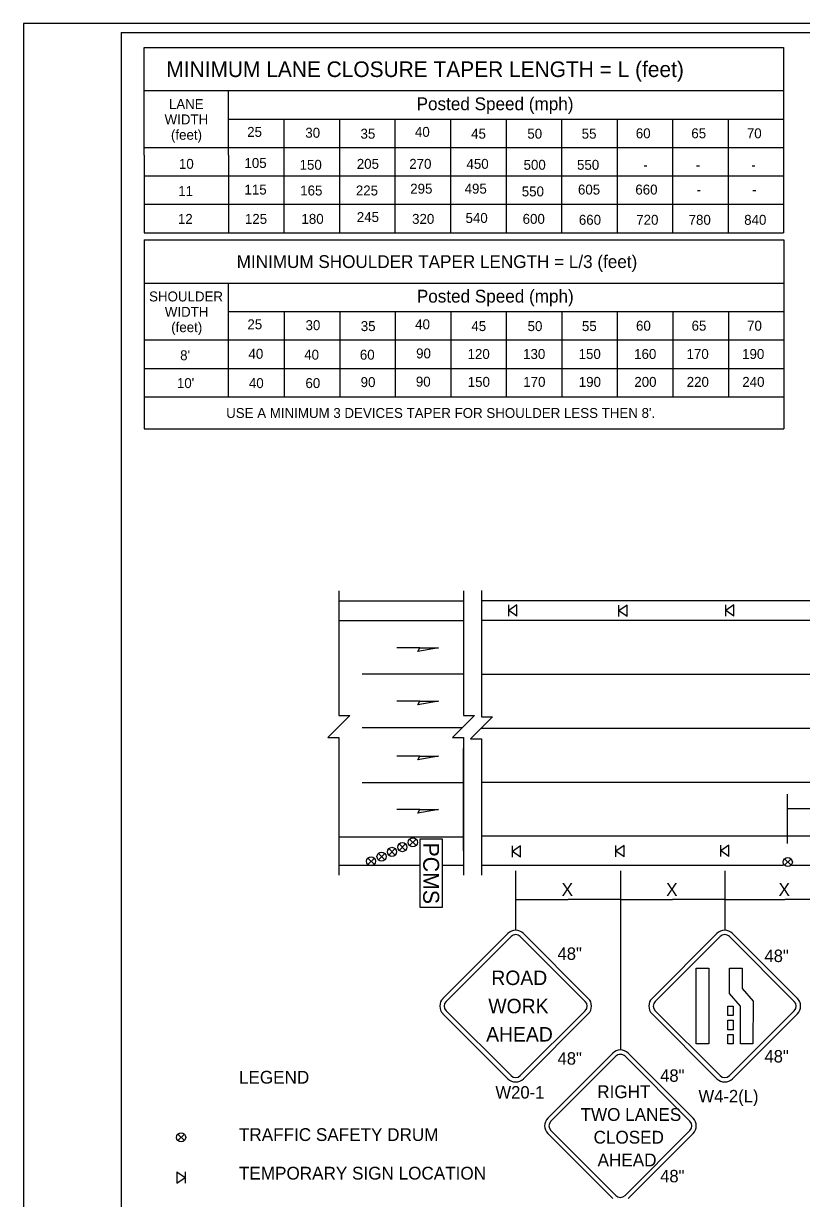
# Model space of a CAD drawing. Extents: x 99988 to 100172, y 99995 to 100047.
# Drawn here: x 99999.31 to 100004.79, y 100002.17 to 100010.44 of the extents above; entities that cross this region are included whole.
import ezdxf

# ---------------------------------------------------------------- set-up
doc = ezdxf.new("R2010")
doc.units = 0
for name, color, linetype in [('Default', 7, 'Continuous'), ('Level 15', 7, 'Continuous'), ('Level 20', 7, 'Continuous'), ('SH_DE_DetailBody1Text', 7, 'Continuous'), ('SH_DE_DetailHeading2Text', 7, 'Continuous'), ('SH_GI_PlotLimits', 7, 'Continuous'), ('SH_GI_SheetBorder', 7, 'Continuous'), ('SH_GI_TrafficMvmntArrowRt1Lane', 7, 'Continuous'), ('SH_TI_MinTaperLength25to35Note', 7, 'Continuous'), ('SH_TI_MinTaperLength25to70Note', 7, 'Continuous'), ('TR_SN_WarningSigns', 7, 'Continuous'), ('TR_WZ_PortableChangeMessageSign', 7, 'Continuous'), ('TR_WZ_WorkZoneDetails', 7, 'Continuous')]:
    doc.layers.add(name, color=color, linetype=linetype)

msp = doc.modelspace()

# ---------------------------------------------------------------- linework, layer by layer
at = {"layer": 'Default'}
for p, q in [((100002.7845, 100006.3463), (100002.7267, 100006.3061)), ((100002.7267, 100006.2659), (100002.7267, 100006.3463)), ((100002.7845, 100006.2659), (100002.7845, 100006.3463)), ((100003.5589, 100006.3444), (100003.5012, 100006.3041)), ((100003.5012, 100006.264), (100003.5012, 100006.3444)), ((100003.5589, 100006.264), (100003.5589, 100006.3444)), ((100004.3113, 100006.3463), (100004.2535, 100006.3061)), ((100004.2535, 100006.2659), (100004.2535, 100006.3463)), ((100004.3113, 100006.2659), (100004.3113, 100006.3463)), ((100002.7845, 100006.2659), (100002.7267, 100006.3061)), ((100003.5589, 100006.264), (100003.5012, 100006.3041)), ((100004.3113, 100006.2659), (100004.2535, 100006.3061)), ((100001.6952, 100005.8622), (100002.4121, 100005.8622)), ((100002.5342, 100005.8585), (100011.4419, 100005.8585)), ((100001.6952, 100005.4826), (100002.4024, 100005.4826)), ((100002.5316, 100005.4785), (100014.1914, 100005.4785)), ((100001.6952, 100005.0976), (100002.4092, 100005.0976)), ((100002.5342, 100005.0998), (100011.6853, 100005.0998)), ((100001.956, 100004.619), (100002.0013, 100004.6643)), ((100002.0013, 100004.619), (100001.956, 100004.6643)), ((100002.0294, 100004.6523), (100002.0747, 100004.6976)), ((100002.0747, 100004.6523), (100002.0294, 100004.6976)), ((100004.2763, 100004.6556), (100004.2186, 100004.6153)), ((100004.2186, 100004.5751), (100004.2186, 100004.6556)), ((100004.2763, 100004.5751), (100004.2763, 100004.6556)), ((100001.8092, 100004.5525), (100001.8545, 100004.5978)), ((100001.8545, 100004.5525), (100001.8092, 100004.5978)), ((100001.8826, 100004.5858), (100001.9279, 100004.631)), ((100001.9279, 100004.5858), (100001.8826, 100004.631)), ((100002.81, 100004.6508), (100002.7523, 100004.6105)), ((100002.7523, 100004.5703), (100002.7523, 100004.6508)), ((100002.81, 100004.5703), (100002.7523, 100004.6105)), ((100002.81, 100004.5703), (100002.81, 100004.6508)), ((100003.5389, 100004.6543), (100003.4812, 100004.614)), ((100003.4812, 100004.5739), (100003.4812, 100004.6543)), ((100003.5389, 100004.5739), (100003.4812, 100004.614)), ((100003.5389, 100004.5739), (100003.5389, 100004.6543)), ((100004.2763, 100004.5751), (100004.2186, 100004.6153)), ((100001.7358, 100004.5192), (100001.7811, 100004.5645)), ((100001.7811, 100004.5192), (100001.7358, 100004.5645)), ((100004.7129, 100004.5589), (100004.6677, 100004.5137)), ((100004.6677, 100004.5589), (100004.7129, 100004.5137)), ((100000.4442, 100002.5769), (100000.3989, 100002.6222)), ((100000.4442, 100002.6222), (100000.3989, 100002.5769)), ((100000.3916, 100002.3575), (100000.4494, 100002.3174)), ((100000.3916, 100002.3575), (100000.3916, 100002.2771)), ((100000.4494, 100002.3575), (100000.4494, 100002.2771)), ((100000.3916, 100002.2771), (100000.4494, 100002.3174))]:
    msp.add_line(p, q, dxfattribs=at)
for centre in [(100001.9786, 100004.6417), (100002.052, 100004.6749), (100001.7584, 100004.5419), (100001.8318, 100004.5751), (100001.9052, 100004.6084), (100004.6903, 100004.5363), (100000.4216, 100002.5995)]:
    msp.add_circle(centre, 0.032, dxfattribs=at)
at = {"layer": 'Level 15'}
for p, q in [((100004.6854, 100004.9138), (100004.8899, 100004.9138)), ((100002.7755, 100004.2732), (100003.144, 100004.2732)), ((100003.5125, 100004.2732), (100003.144, 100004.2732)), ((100003.5125, 100004.2732), (100003.8795, 100004.2732)), ((100004.2465, 100004.2732), (100003.8795, 100004.2732)), ((100004.2465, 100004.2732), (100004.6704, 100004.2732)), ((100005.0944, 100004.2732), (100004.6704, 100004.2732))]:
    msp.add_line(p, q, dxfattribs=at)
at = {"layer": 'SH_GI_PlotLimits'}
msp.add_lwpolyline([(99999.3125, 99999.9375), (100015.8125, 99999.9375), (100015.8125, 100010.4375), (99999.3125, 100010.4375)], close=True, dxfattribs=at)
at = {"layer": 'SH_GI_SheetBorder'}
for q in [(100000, 100000), (100015.75, 100010.375)]:
    msp.add_line((100000, 100010.375), q, dxfattribs=at)
at = {"layer": 'SH_GI_TrafficMvmntArrowRt1Lane'}
for p, q in [((100002.1012, 100006.0451), (100001.9404, 100006.0451)), ((100002.1012, 100005.6684), (100001.9404, 100005.6684)), ((100002.1012, 100005.2821), (100001.9404, 100005.2821)), ((100002.1012, 100004.9072), (100001.9404, 100004.9072))]:
    msp.add_line(p, q, dxfattribs=at)
for points in [[(100002.2322, 100006.0451), (100002.0863, 100006.0194), (100002.1012, 100006.0451)], [(100002.2322, 100005.6684), (100002.0863, 100005.6427), (100002.1012, 100005.6684)], [(100002.2322, 100005.2821), (100002.0863, 100005.2563), (100002.1012, 100005.2821)], [(100002.2322, 100004.9072), (100002.0863, 100004.8815), (100002.1012, 100004.9072)]]:
    msp.add_lwpolyline(points, close=True, dxfattribs=at)
at = {"layer": 'SH_TI_MinTaperLength25to35Note'}
for p, q in [((100000.1627, 100008.9145), (100004.6627, 100008.9145)), ((100000.1627, 100008.9145), (100000.1627, 100008.2042)), ((100004.6627, 100008.9145), (100004.6627, 100008.2042)), ((100000.1627, 100008.6113), (100004.6627, 100008.6113)), ((100000.7559, 100008.2042), (100000.7559, 100008.6113)), ((100000.7559, 100008.4113), (100004.6627, 100008.4113)), ((100001.1465, 100008.4113), (100001.1465, 100008.2042)), ((100001.5372, 100008.4113), (100001.5372, 100008.2042)), ((100001.9279, 100008.4113), (100001.9279, 100008.2042)), ((100002.3186, 100008.4113), (100002.3186, 100008.2042)), ((100002.7093, 100008.4113), (100002.7093, 100008.2042)), ((100003.1, 100008.4113), (100003.1, 100008.2042)), ((100003.4907, 100008.4113), (100003.4907, 100008.2042)), ((100003.8813, 100008.4113), (100003.8813, 100008.2042)), ((100004.2719, 100008.4113), (100004.2719, 100008.2042)), ((100000.1627, 100008.2113), (100004.6627, 100008.2113)), ((100000.1627, 100008.2042), (100000.1627, 100007.5845)), ((100000.7559, 100007.8096), (100000.7559, 100008.2042)), ((100001.1465, 100008.2042), (100001.1465, 100007.8096)), ((100001.5372, 100008.2042), (100001.5372, 100007.8096)), ((100001.9279, 100008.2042), (100001.9279, 100007.8096)), ((100002.3186, 100008.2042), (100002.3186, 100007.8096)), ((100002.7093, 100008.2042), (100002.7093, 100007.8096)), ((100003.1, 100008.2042), (100003.1, 100007.8096)), ((100003.4907, 100008.2042), (100003.4907, 100007.8096)), ((100003.8813, 100008.2042), (100003.8813, 100007.8096)), ((100004.2719, 100008.2042), (100004.2719, 100007.8096)), ((100004.6627, 100008.2042), (100004.6627, 100007.5845)), ((100000.1627, 100008.0096), (100004.6627, 100008.0096)), ((100000.1627, 100007.8096), (100004.6627, 100007.8096)), ((100000.1627, 100007.5845), (100004.6627, 100007.5845))]:
    msp.add_line(p, q, dxfattribs=at)
at = {"layer": 'SH_TI_MinTaperLength25to70Note'}
for p, q in [((100000.1611, 100010.2684), (100004.6611, 100010.2684)), ((100000.1611, 100009.5102), (100000.1611, 100010.2684)), ((100004.6611, 100010.2684), (100004.6611, 100008.9652)), ((100000.1611, 100009.9652), (100004.6611, 100009.9652)), ((100000.7542, 100009.5102), (100000.7542, 100009.9652)), ((100000.7542, 100009.7652), (100004.6611, 100009.7652)), ((100001.1449, 100009.7652), (100001.1449, 100008.9652)), ((100001.5356, 100009.7652), (100001.5356, 100008.9652)), ((100001.9263, 100009.7652), (100001.9263, 100008.9652)), ((100002.3169, 100009.7652), (100002.3169, 100008.9652)), ((100002.7076, 100009.7652), (100002.7076, 100008.9652)), ((100003.0983, 100009.7652), (100003.0983, 100008.9652)), ((100003.489, 100009.7652), (100003.489, 100008.9652)), ((100003.8796, 100009.7652), (100003.8796, 100008.9652)), ((100004.2703, 100009.7652), (100004.2703, 100008.9652)), ((100000.1611, 100009.5652), (100004.6611, 100009.5652)), ((100000.1611, 100009.5102), (100000.1611, 100008.9652)), ((100000.7542, 100009.5102), (100000.7542, 100008.9652)), ((100000.1611, 100009.3652), (100004.6611, 100009.3652)), ((100000.1611, 100009.1652), (100004.6611, 100009.1652)), ((100000.1611, 100008.9652), (100004.6611, 100008.9652))]:
    msp.add_line(p, q, dxfattribs=at)
at = {"layer": 'TR_SN_WarningSigns'}
for p, q in [((100002.2642, 100003.5777), (100002.7212, 100004.0346)), ((100002.286, 100003.556), (100002.7429, 100004.0129)), ((100002.8082, 100004.0129), (100003.2651, 100003.5559)), ((100002.8299, 100004.0346), (100003.2868, 100003.5777)), ((100003.7351, 100003.5777), (100004.1921, 100004.0346)), ((100003.7569, 100003.556), (100004.2138, 100004.0129)), ((100004.2791, 100004.0129), (100004.736, 100003.556)), ((100004.3009, 100004.0346), (100004.7577, 100003.5777)), ((100002.7211, 100003.012), (100002.2642, 100003.4689)), ((100002.7429, 100003.0338), (100002.286, 100003.4907)), ((100003.2651, 100003.4907), (100002.8082, 100003.0338)), ((100003.2868, 100003.4689), (100002.8299, 100003.012)), ((100004.1921, 100003.0121), (100003.7351, 100003.4689)), ((100004.2138, 100003.0338), (100003.7569, 100003.4907)), ((100004.736, 100003.4907), (100004.2791, 100003.0338)), ((100004.7577, 100003.4689), (100004.3009, 100003.0121)), ((100003.0011, 100002.7348), (100003.4581, 100003.1917)), ((100003.0229, 100002.7131), (100003.4798, 100003.17)), ((100003.5451, 100003.17), (100004.002, 100002.7131)), ((100003.5668, 100003.1917), (100004.0237, 100002.7348)), ((100003.4581, 100002.1692), (100003.0011, 100002.626)), ((100003.4798, 100002.1909), (100003.0229, 100002.6478)), ((100004.002, 100002.6478), (100003.5451, 100002.1909)), ((100004.0237, 100002.626), (100003.5668, 100002.1692))]:
    msp.add_line(p, q, dxfattribs=at)
for points in [[(100004.135, 100003.2567), (100004.0454, 100003.2567), (100004.0454, 100003.79), (100004.135, 100003.79)], [(100004.3696, 100003.79), (100004.3696, 100003.6462), (100004.4475, 100003.557), (100004.4436, 100003.2567), (100004.3579, 100003.2567), (100004.3579, 100003.5234), (100004.2801, 100003.6126), (100004.2801, 100003.79)], [(100004.3068, 100003.4567), (100004.2673, 100003.4567), (100004.2673, 100003.5233), (100004.3068, 100003.5233)], [(100004.3068, 100003.3567), (100004.2673, 100003.3567), (100004.2673, 100003.4233), (100004.3068, 100003.4233)], [(100004.3068, 100003.2567), (100004.2673, 100003.2567), (100004.2673, 100003.3233), (100004.3068, 100003.3233)]]:
    msp.add_lwpolyline(points, close=True, dxfattribs=at)
for centre, radius, start, end in [((100002.7755, 100003.9802), 0.0769, 44.99627, 134.99965), ((100002.7755, 100003.9802), 0.0462, 44.99627, 134.99965), ((100004.2465, 100003.9802), 0.0769, 44.99627, 134.99965), ((100004.2465, 100003.9802), 0.0462, 44.99627, 134.99965), ((100002.3186, 100003.5233), 0.0769, 134.99657, 224.99357), ((100002.3186, 100003.5233), 0.0462, 134.99657, 224.99357), ((100003.2324, 100003.5233), 0.0462, 314.99936, 44.99485), ((100003.2324, 100003.5233), 0.0769, 314.99936, 44.99485), ((100003.7896, 100003.5233), 0.0769, 134.99657, 224.99357), ((100003.7896, 100003.5233), 0.0462, 134.99657, 224.99357), ((100004.7034, 100003.5233), 0.0462, 314.99936, 44.99485), ((100004.7034, 100003.5233), 0.0769, 314.99936, 44.99485), ((100003.5125, 100003.1373), 0.0769, 44.99627, 134.99965), ((100003.5125, 100003.1373), 0.0462, 44.99627, 134.99965), ((100002.7755, 100003.0664), 0.0769, 225, 314.99958), ((100002.7755, 100003.0664), 0.0462, 225, 314.99958), ((100004.2464, 100003.0664), 0.0769, 225, 314.99958), ((100004.2464, 100003.0664), 0.0462, 225, 314.99958), ((100003.0556, 100002.6804), 0.0769, 134.99657, 224.99357), ((100003.0556, 100002.6804), 0.0462, 134.99657, 224.99357), ((100003.9693, 100002.6804), 0.0462, 314.99936, 44.99485), ((100003.9693, 100002.6804), 0.0769, 314.99936, 44.99485), ((100003.5124, 100002.2235), 0.0462, 225, 314.99958)]:
    msp.add_arc(centre, radius, start, end, dxfattribs=at)
at = {"layer": 'TR_WZ_PortableChangeMessageSign'}
msp.add_lwpolyline([(100002.1008, 100004.6986), (100002.1008, 100004.2186), (100002.2608, 100004.2186), (100002.2608, 100004.6986)], close=True, dxfattribs=at)
at = {"layer": 'TR_WZ_WorkZoneDetails'}
for p, q in [((100001.5316, 100006.3745), (100002.4092, 100006.3745)), ((100002.5342, 100006.3767), (100014.2093, 100006.3767)), ((100001.5365, 100006.2357), (100002.4092, 100006.2357)), ((100002.5342, 100006.2379), (100009.125, 100006.2379)), ((100002.4092, 100004.615), (100002.4092, 100005.3363)), ((100004.6854, 100005.0138), (100004.6854, 100004.6683)), ((100001.5316, 100004.7142), (100002.4092, 100004.7142)), ((100002.5342, 100004.7201), (100005.0601, 100004.7201)), ((100001.5316, 100004.5142), (100002.0987, 100004.5142)), ((100002.2608, 100004.5142), (100002.4092, 100004.5142)), ((100002.5342, 100004.5142), (100004.658, 100004.5142)), ((100004.7166, 100004.5142), (100005.3535, 100004.5142)), ((100002.7755, 100004.4751), (100002.7755, 100004.0572)), ((100003.5125, 100004.4751), (100003.5125, 100003.2143)), ((100004.2465, 100004.4751), (100004.2465, 100004.0572))]:
    msp.add_line(p, q, dxfattribs=at)
for points in [[(100001.5316, 100006.4453), (100001.5316, 100005.5668), (100001.609, 100005.5668), (100001.4542, 100005.412), (100001.5316, 100005.412), (100001.5316, 100004.4434)], [(100002.4092, 100006.4453), (100002.4092, 100005.5668), (100002.4866, 100005.5668), (100002.3318, 100005.412), (100002.4092, 100005.412), (100002.4092, 100004.4434)], [(100002.5342, 100006.4475), (100002.5342, 100005.5586), (100002.6116, 100005.5586), (100002.4568, 100005.4037), (100002.5342, 100005.4037), (100002.5342, 100004.4434)]]:
    msp.add_lwpolyline(points, dxfattribs=at)

# ---------------------------------------------------------------- texts
at = {"layer": 'Level 20'}
for p in [(100003.0989, 100004.2982), (100003.8344, 100004.2982), (100004.6254, 100004.2982)]:
    msp.add_text('X', height=0.09, dxfattribs=at).set_placement(p)
at = {"layer": 'SH_DE_DetailBody1Text'}
for s, p in [('TRAFFIC SAFETY DRUM', (100000.8284, 100002.5738)), ('TEMPORARY SIGN LOCATION', (100000.8284, 100002.3023))]:
    msp.add_text(s, height=0.09, dxfattribs=at).set_placement(p)
at = {"layer": 'SH_DE_DetailHeading2Text'}
msp.add_text('LEGEND', height=0.09, dxfattribs=at).set_placement((100000.8284, 100002.9775))
at = {"layer": 'SH_TI_MinTaperLength25to35Note'}
for s, height, p in [('MINIMUM SHOULDER TAPER LENGTH = L/3 (feet)', 0.09, (100000.8125, 100008.7169)), ('SHOULDER', 0.07, (100000.1961, 100008.4817)), ('Posted Speed (mph)', 0.09, (100002.0802, 100008.4737)), ('WIDTH', 0.07, (100000.307, 100008.3736)), ('(feet)', 0.07, (100000.3518, 100008.2656)), ('25', 0.07, (100000.888, 100008.2858)), ('30', 0.07, (100001.2971, 100008.2796)), ('35', 0.07, (100001.6856, 100008.2731)), ('40', 0.07, (100002.0684, 100008.2858)), ('45', 0.07, (100002.4638, 100008.2731)), ('50', 0.07, (100002.8594, 100008.2731)), ('55', 0.07, (100003.2417, 100008.2731)), ('60', 0.07, (100003.6225, 100008.2758)), ('65', 0.07, (100004.0132, 100008.2758)), ('70', 0.07, (100004.4039, 100008.2758)), ("8'", 0.07, (100000.4148, 100008.0679)), ('40', 0.07, (100000.8955, 100008.0783)), ('40', 0.07, (100001.2877, 100008.0717)), ('60', 0.07, (100001.6792, 100008.0717)), ('90', 0.07, (100002.075, 100008.0809)), ('120', 0.07, (100002.4371, 100008.0769)), ('130', 0.07, (100002.8278, 100008.0769)), ('150', 0.07, (100003.2184, 100008.0769)), ('160', 0.07, (100003.6091, 100008.0769)), ('170', 0.07, (100003.9778, 100008.0769)), ('190', 0.07, (100004.3688, 100008.0769)), ("10'", 0.07, (100000.3919, 100007.8719)), ('40', 0.07, (100000.8984, 100007.8719)), ('60', 0.07, (100001.2964, 100007.8719)), ('90', 0.07, (100001.6847, 100007.879)), ('90', 0.07, (100002.0733, 100007.8822)), ('150', 0.07, (100002.4383, 100007.8805)), ('170', 0.07, (100002.8289, 100007.8805)), ('190', 0.07, (100003.2196, 100007.8805)), ('200', 0.07, (100003.6103, 100007.8805)), ('220', 0.07, (100003.979, 100007.8805)), ('240', 0.07, (100004.37, 100007.8805)), ("USE A MINIMUM 3 DEVICES TAPER FOR SHOULDER LESS THEN 8'.", 0.07, (100000.7386, 100007.6618))]:
    msp.add_text(s, height=height, dxfattribs=at).set_placement(p)
at = {"layer": 'SH_TI_MinTaperLength25to70Note'}
for s, height, p in [('MINIMUM LANE CLOSURE TAPER LENGTH = L (feet)', 0.11, (100000.3178, 100010.0608)), ('LANE', 0.07, (100000.3356, 100009.8356)), ('Posted Speed (mph)', 0.09, (100002.0785, 100009.8276)), ('WIDTH', 0.07, (100000.3053, 100009.7275)), ('25', 0.07, (100000.8863, 100009.6397)), ('30', 0.07, (100001.2954, 100009.6335)), ('40', 0.07, (100002.0668, 100009.6397)), ('60', 0.07, (100003.6209, 100009.6297)), ('65', 0.07, (100004.0116, 100009.6297)), ('70', 0.07, (100004.4022, 100009.6297)), ('(feet)', 0.07, (100000.3501, 100009.6195)), ('35', 0.07, (100001.6839, 100009.627)), ('45', 0.07, (100002.4622, 100009.627)), ('50', 0.07, (100002.8578, 100009.627)), ('55', 0.07, (100003.2401, 100009.627)), ('10', 0.07, (100000.4062, 100009.4147)), ('105', 0.07, (100000.8671, 100009.4209)), ('150', 0.07, (100001.2552, 100009.4081)), ('205', 0.07, (100001.6576, 100009.4147)), ('270', 0.07, (100002.0267, 100009.4147)), ('450', 0.07, (100002.4293, 100009.4147)), ('500', 0.07, (100002.8311, 100009.4081)), ('550', 0.07, (100003.2072, 100009.4081)), ('-', 0.07, (100003.6736, 100009.4081)), ('-', 0.07, (100004.0423, 100009.4081)), ('-', 0.07, (100004.4333, 100009.4081)), ('11', 0.07, (100000.4012, 100009.2235)), ('115', 0.07, (100000.8674, 100009.2339)), ('165', 0.07, (100001.2595, 100009.2274)), ('225', 0.07, (100001.6511, 100009.2274)), ('295', 0.07, (100002.0337, 100009.2401)), ('495', 0.07, (100002.4163, 100009.2401)), ('550', 0.07, (100002.8184, 100009.2208)), ('605', 0.07, (100003.2139, 100009.2339)), ('660', 0.07, (100003.6176, 100009.2339)), ('-', 0.07, (100004.049, 100009.2339)), ('-', 0.07, (100004.44, 100009.2339)), ('12', 0.07, (100000.3988, 100009.0275)), ('125', 0.07, (100000.8703, 100009.0275)), ('180', 0.07, (100001.2683, 100009.0275)), ('245', 0.07, (100001.6577, 100009.0406)), ('320', 0.07, (100002.0467, 100009.0275)), ('540', 0.07, (100002.4227, 100009.0341)), ('600', 0.07, (100002.8246, 100009.0275)), ('660', 0.07, (100003.2201, 100009.021)), ('720', 0.07, (100003.6238, 100009.021)), ('780', 0.07, (100003.9925, 100009.021)), ('840', 0.07, (100004.3834, 100009.021))]:
    msp.add_text(s, height=height, dxfattribs=at).set_placement(p)
at = {"layer": 'TR_SN_WarningSigns'}
for s, height, p in [('48"', 0.0875, (100003.07, 100003.8481)), ('48"', 0.0875, (100004.526, 100003.8331)), ('ROAD', 0.10176, (100002.6043, 100003.6712)), ('WORK', 0.10176, (100002.5833, 100003.4725)), ('AHEAD', 0.10176, (100002.568, 100003.2738)), ('48"', 0.0875, (100003.07, 100003.1111)), ('48"', 0.0875, (100004.526, 100003.126)), ('48"', 0.0875, (100003.792, 100002.9902)), ('W20-1', 0.0875, (100002.6331, 100002.8727)), ('RIGHT ', 0.09, (100003.3495, 100002.8754)), ('W4-2(L)', 0.0875, (100004.0616, 100002.8458)), ('TWO LANES', 0.09, (100003.2318, 100002.7154)), ('CLOSED', 0.09, (100003.3237, 100002.5554)), ('AHEAD', 0.09, (100003.3519, 100002.3954)), ('48"', 0.0875, (100003.792, 100002.2831))]:
    msp.add_text(s, height=height, rotation=360, dxfattribs=at).set_placement(p)
at = {"layer": 'TR_WZ_PortableChangeMessageSign'}
msp.add_text('PCMS', height=0.112, rotation=270, dxfattribs=at).set_placement((100002.1248, 100004.6741))

doc.saveas('drawing.dxf')
